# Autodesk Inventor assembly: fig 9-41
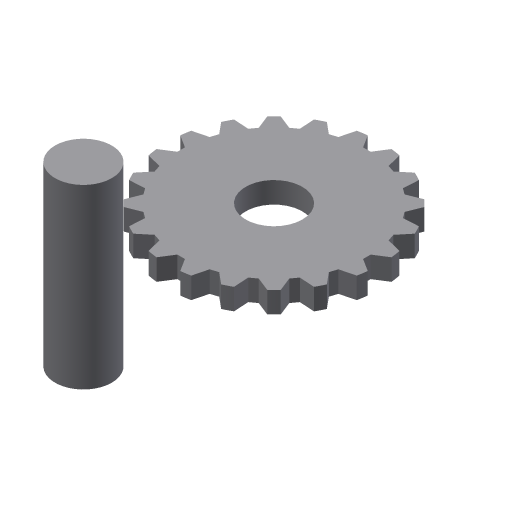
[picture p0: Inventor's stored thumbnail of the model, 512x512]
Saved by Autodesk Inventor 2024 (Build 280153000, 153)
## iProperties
Created: 2013-07
Part Number: fig 9-41
Document SubType Name: Assembly
Designer: CADCIM
Author: CADCIM
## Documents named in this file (3)
- D:\PROJECTS\Project 2023\RESOURCES INVENTOR 2024\RESOURCES INVENTOR 2024\Inventor_2023_Part\Inventor_2024_Part\c09_Inv_2024_prt\fig 9-42.iam
- D:\PROJECTS\Project 2023\RESOURCES INVENTOR 2024\RESOURCES INVENTOR 2024\Inventor_2023_Part\Inventor_2024_Part\c09_Inv_2024_prt\13.ipt
- D:\PROJECTS\Project 2023\RESOURCES INVENTOR 2024\RESOURCES INVENTOR 2024\Inventor_2023_Part\Inventor_2024_Part\c09_Inv_2024_prt\14.ipt
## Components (2 placed, 2 different names)
1. 13:1
2. 14:1
